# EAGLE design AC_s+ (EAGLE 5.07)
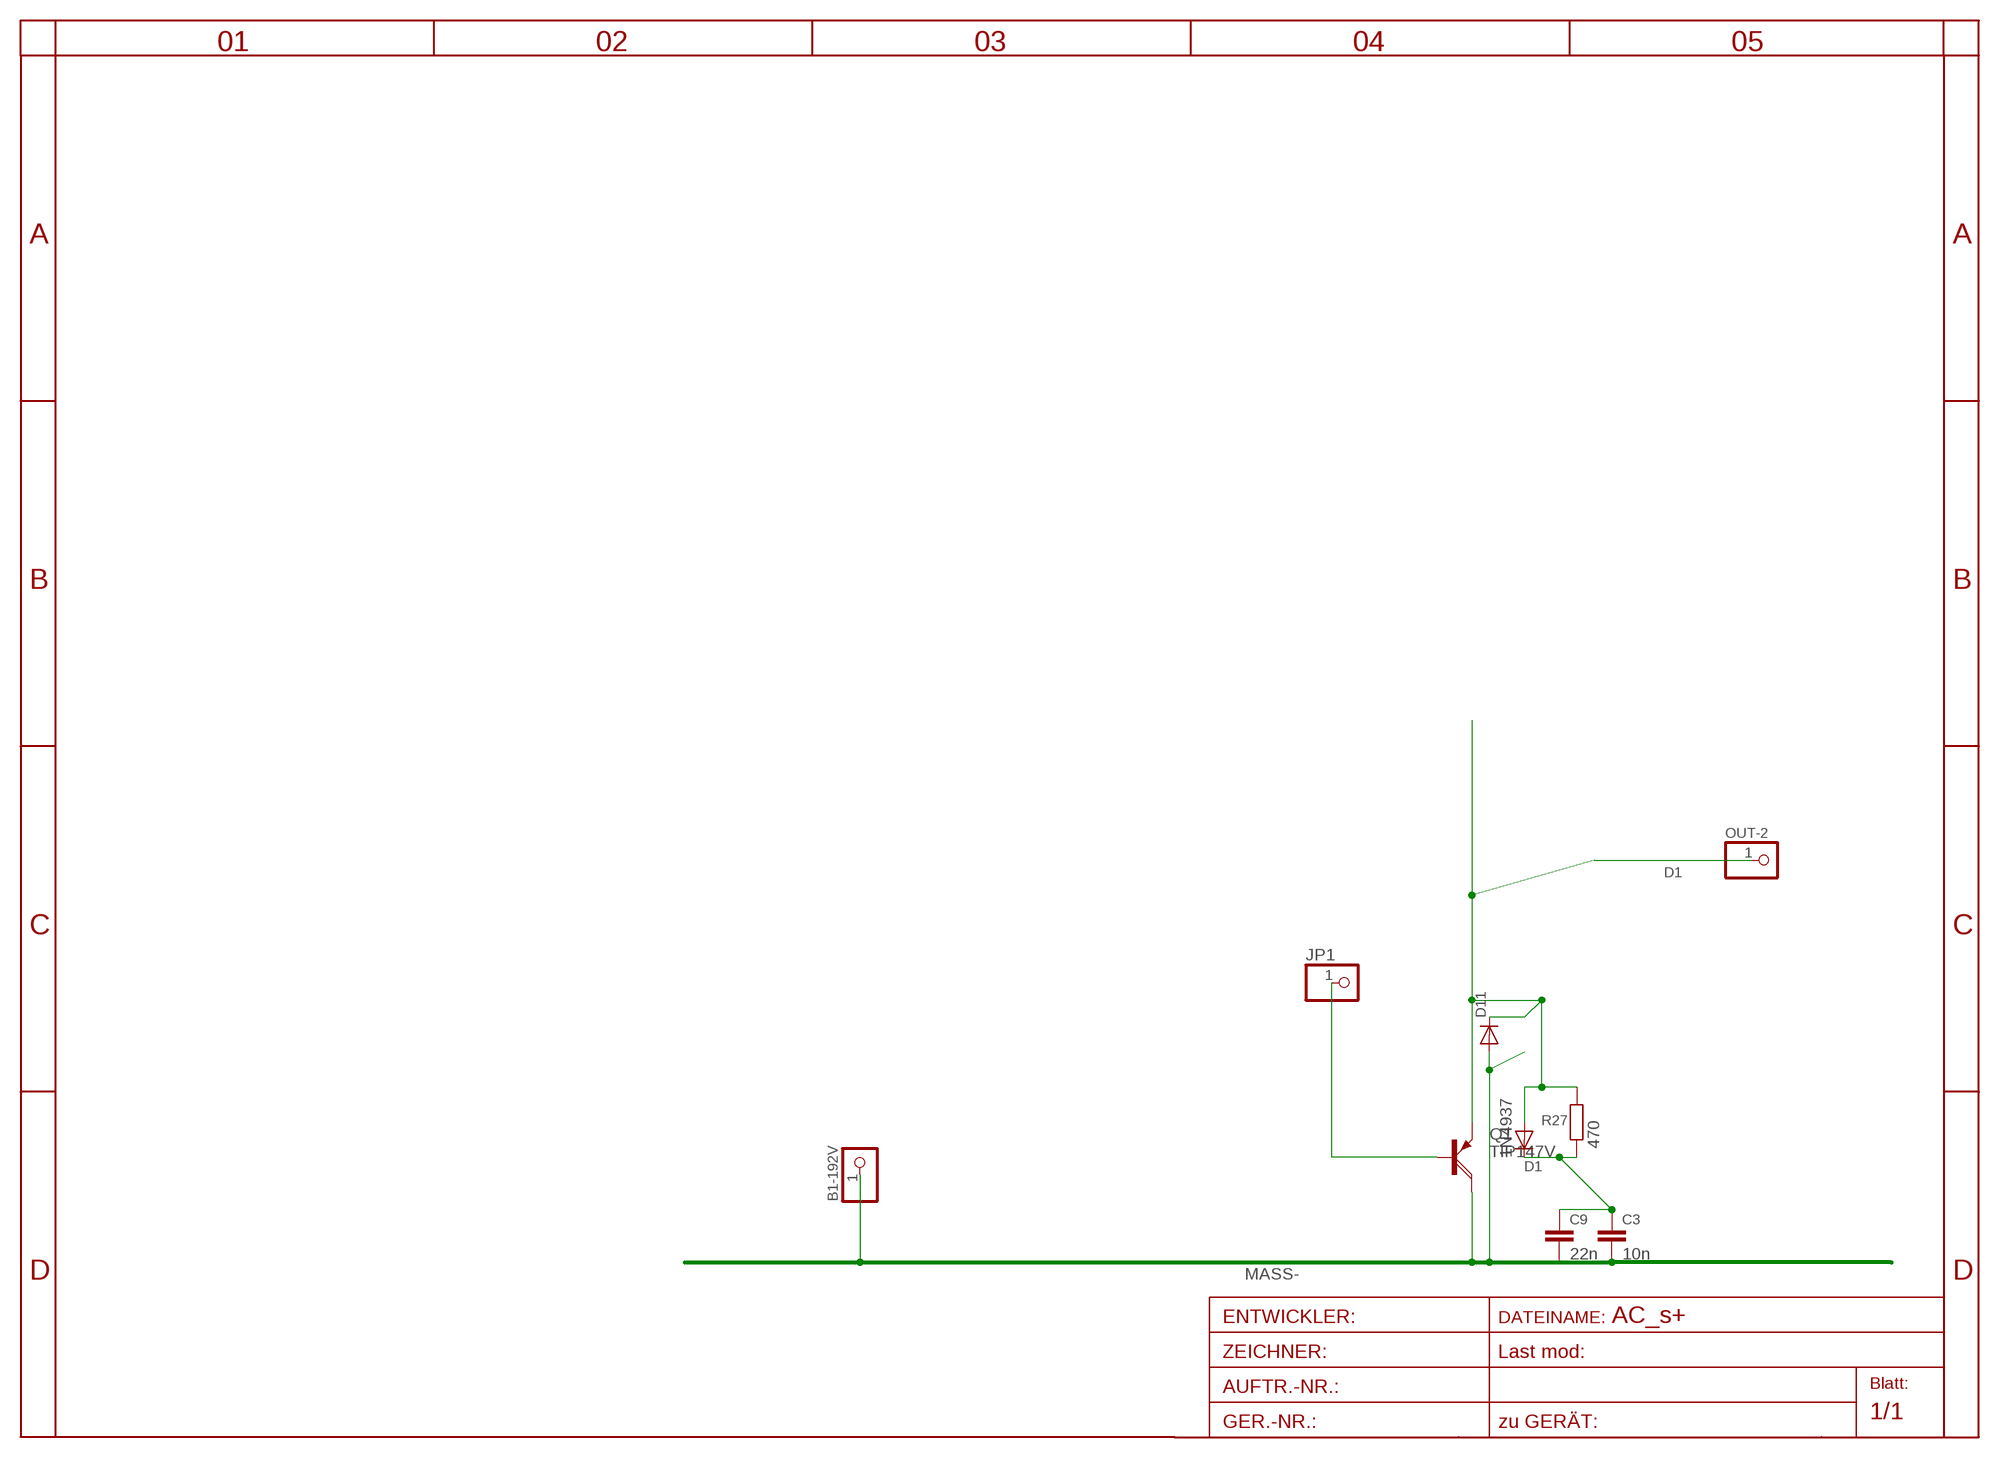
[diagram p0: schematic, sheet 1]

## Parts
B1-192V  PINHD-1X13MM2  [1X3MM2]
C3  10n  C-EU025_050-050X075  [C025_050-050X075]
C9  22n  C-EU102-043X133  [C102-043X133]
D1  1N4937  1N4004DO41-10  [DO41-10]
D11  DIODE-SMC  [SMC]
JP1  PINHD-1X11X0.4  [1X01]
OUT-2  PINHD-1X13MM2  [1X3MM2]
Q1  TIP147V  [SOT93V]
R27  470  R-EU_0207/10  [0207/10]

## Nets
D1: D1.A D11.C OUT-2.1 Q1.E R27.2
MASS-: B1-192V.1 C3.3 C9.2 D11.A Q1.C
N$2: C3.1 C9.1 D1.C R27.1
N$3: JP1.1 Q1.B

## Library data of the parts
B1-192V JP1 OUT-2 = pinhead:PINHD-1X1: PIN HEADER
C3 C9 = rcl-2:C-EU: CAPACITOR, European symbol
D1 = diode:1N4004: DIODE
D11 = diode:DIODE-: DIODE
Q1 = transistor-power:TIP147: PNP DARLINGTON TRANSISTOR
R27 = rcl-2:R-EU_: RESISTOR, European symbol

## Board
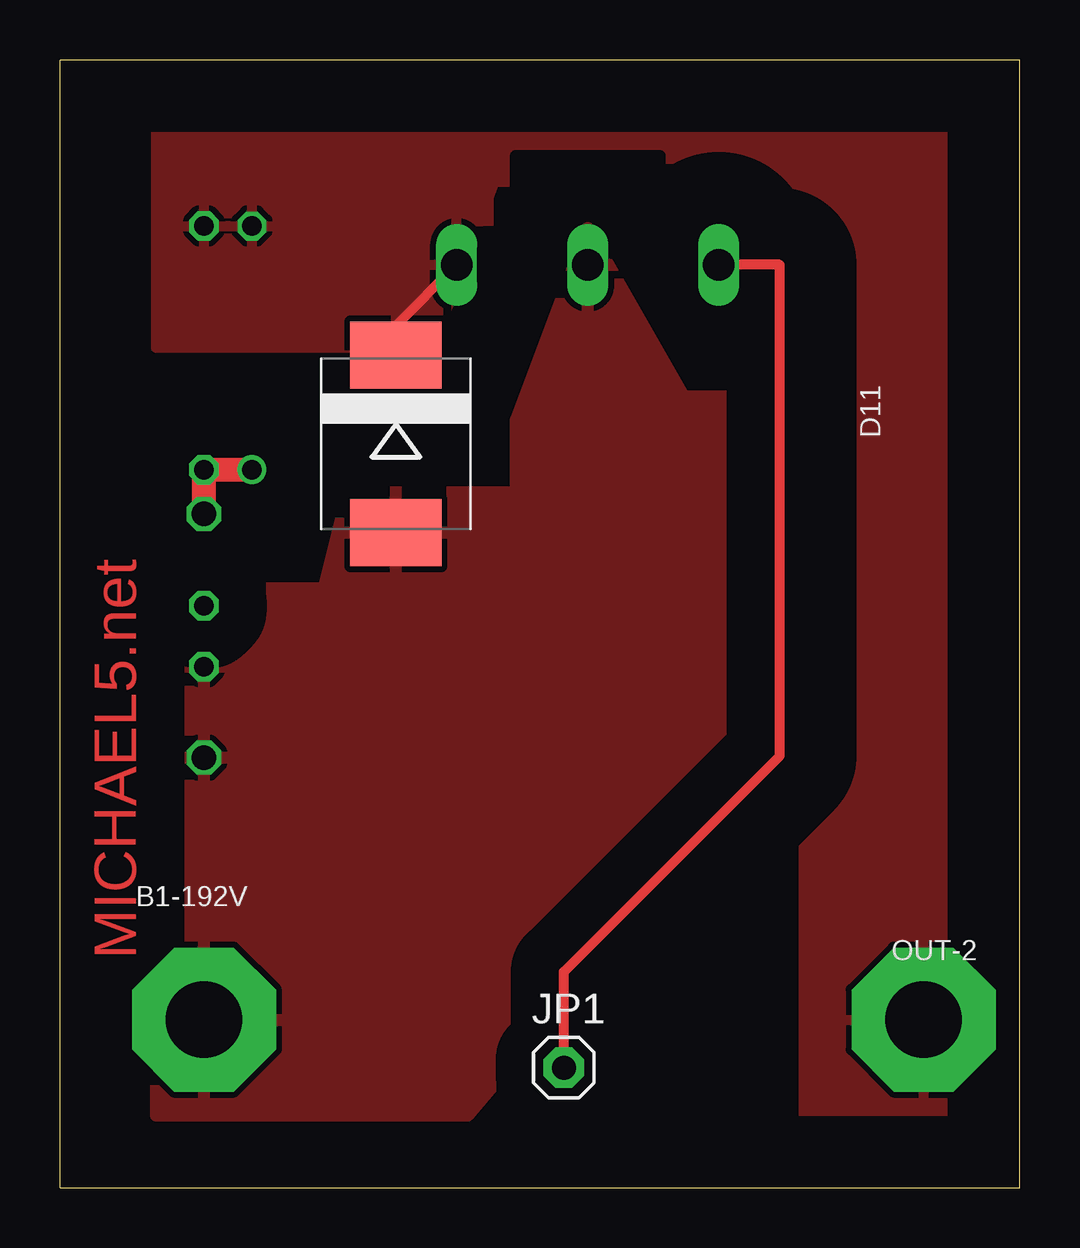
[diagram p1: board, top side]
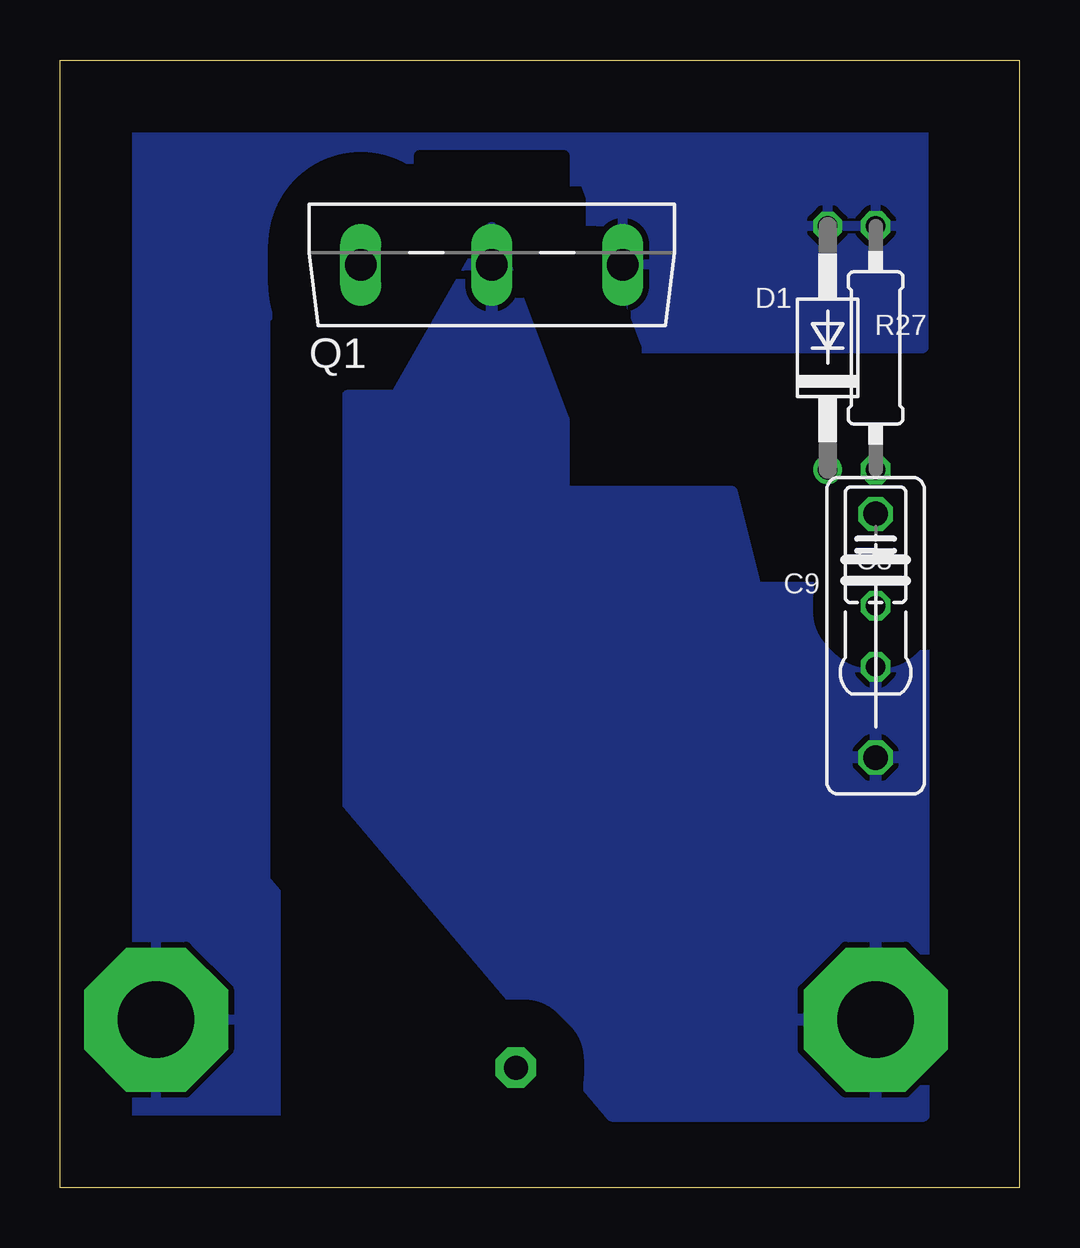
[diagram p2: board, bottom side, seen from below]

Size 40 x 47 mm. Coordinates in mm from the lower left corner, seen from the top.
Outline: 0,0 40,0 40,47 0,47 0,0
Copper layers (1*16): Top 0.035mm / dielectric 1.5mm / Bottom 0.035mm
Design rules "default *": minimum track width 12mil, minimum drill 24mil, track to track 8mil, track to pad 8mil, pad to pad 8mil, via to via 8mil, smd to smd 8mil, copper to edge 40mil, drill to drill 8mil, minimum pad ring 8mil, minimum via ring 8mil, stop-mask expansion 4mil, vias tented up to drill 0mil, thermal gap 10mil

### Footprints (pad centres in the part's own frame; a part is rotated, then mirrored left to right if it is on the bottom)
1X3MM2 = drill 3.2 pad 6 octagon: 1 0,0
C025_050-050X075 = drill 0.813 octagon: 1 -3.81,0; 2 0,0; 3 2.54,0
C102-043X133 = drill 1.016 octagon: 1 -5.08,0; 2 5.08,0
DO41-10 = drill 0.8 octagon: A 5.08,0 | drill 0.8 round: C -5.08,0
SMC = smd 2.8 x 3.8: A 3.7,0; C -3.7,0
1X01 = drill 1 pad 1.676 octagon: 1 0,0
SOT93V = drill 1.3 pad 1.676 long: B -5.461,-2.54; C 0,-2.54; E 5.461,-2.54
0207/10 = drill 0.813 octagon: 1 -5.08,0; 2 5.08,0

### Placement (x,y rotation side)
B1-192V  6,7 0 top
C3  6,24.25 270 bottom
C9  6,23 270 bottom
D1  8,35 90 bottom
D11  14,31 270 top
JP1  21,5 0 top
OUT-2  36,7 0 top
Q1  22,41 0 bottom
R27  6,35 90 bottom

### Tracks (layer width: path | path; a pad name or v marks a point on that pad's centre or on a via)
D1
  Top 0.406: D11.C 14,35.92 Q1.E
  pour Top (isolate 3, rank 2): 4,46 39,46 39,3 31,3 31,40 16,35 4,35
  pour Bottom (isolate 3, rank 2): 4,46 39,46 39,3 31,3 31,40 16,35 4,35
MASS-
  pour Top (isolate 2): 4,25 11,25 12,29 19,29 19,32 22,40 26,33 28,33 28,16 17,3 4,3
  pour Bottom (isolate 2): 4,25 11,25 12,29 19,29 19,32 22,40 26,33 28,33 28,16 17,3 4,3
N$2
  Top 1: D1.C R27.1 C9.1 C3.1
N$3
  Top 0.406: Q1.B 30,38.46 30,18 21,9 JP1.1

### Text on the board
Top: MICHAEL5.net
